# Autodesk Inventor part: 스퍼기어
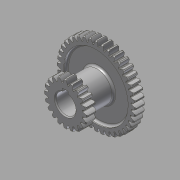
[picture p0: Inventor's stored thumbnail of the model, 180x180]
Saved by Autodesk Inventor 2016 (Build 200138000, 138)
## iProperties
Created: 2015-09
Part Number: 스퍼기어
Material: 강철, 연강
Document SubType Name: Modeling
Designer: mduedu
Density: 7.86 g/cm^3
Mass: 345.726 g
Surface Area: 225.641 cm^2
Volume: 43.9855 cm^3
Appearance: 강철
Author: mduedu
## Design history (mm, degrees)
sketch "스케치1"
  geometry: C1 r 38 at (0, 0); C2 r 40 at (0, 0); C3 r 35.5 at (0, 0); 1 further point
  constraints: 3 centre point, 3 coincident
  dimensions: "d0" = 76 diameter of C1; "d2" = 2 radial gap between concentric circles of C2 C1; "d3" = 71 diameter of C3 (computed from d0)
extrude "돌출1" new body sketch "스케치1" stored distance "d4" = 10; taper "d5" = 0 deg
sketch "스케치2"
  geometry: L1 (0, 35.5)-(0, -35.5); L2 (0, 0)-(40, 0); L3 (0, 0.57)-(39.996, 0.57); L4 (0, 1.57)-(39.969, 1.57); L5 (0, 2.07)-(39.946, 2.07); A1 r 35.5 centre (0, 0) between (0, 35.5) and (0, -35.5) reference; A2 r 40 centre (0, 0) between (40, 0) and (39.946, 2.07) reference; A3 r 9.234 centre (34.93, -7.149) between (39.996, 0.57) and (35.44, 2.07); A4 r 9.234 centre (34.93, 7.149) between (35.44, -2.07) and (39.996, -0.57); A5 r 40 centre (0, 0) between (39.996, -0.57) and (39.996, 0.57); A6 r 35.5 centre (0, 0) between (35.44, -2.07) and (35.44, 2.07); 4 further points
  constraints: 16 point on circle, 10 end point, 6 point on line, 4 centre point, 3 coincident, 3 parallel, 3 symmetric about line, 2 midpoint, 1 perpendicular, 1 vertical, 3 other
  dimensions: "d6" = 0.5 distance between parallel lines of L4 L5; "d8" = 1 distance between parallel lines of L3 L4; "d9" = 1.57 distance between parallel lines of L2 L4
extrude "돌출2" join sketch "스케치2" distance "d10" = 5; taper "d12" = 0 deg; dims "d11" = 5, "d13" = 0
fillet "모깎기1" dims "d17" = 0.5
chamfer "모따기1" distance "d21" = 1; stored, may be unused: second distance "d22" = 2, angle "d23" = 45 deg
sketch "스케치3"
  geometry: C1 r 32.5 at (0, 0); C2 r 15 at (0, 0); 1 further point
  constraints: 2 centre point, 2 coincident
  dimensions: "d27" = 65 diameter of C1; "d28" = 30 diameter of C2
extrude "돌출3" cut sketch "스케치3" distance "d29" = 3; taper "d30" = 0 deg
fillet "모깎기2" dims "d31" = 2
node "작업 평면2"
  node "작업 평면1"
sketch "스케치4"
  geometry: C1 r 15 at (0, 0) reference; 1 further point
extrude "돌출4" join sketch "스케치4" stored distance "d34" = 3; taper "d35" = 0 deg
sketch "스케치5"
  geometry: C1 r 17.5 at (0, 0); C2 r 20 at (0, 0); C3 r 22 at (0, 0); 1 further point
  constraints: 3 centre point, 3 coincident
  dimensions: "d36" = 40 diameter of C2; "d38" = 2 radial gap between concentric circles of C2 C3; "d39" = 35 diameter of C1 (= d36 - 2.5 x d38)
extrude "돌출6" join sketch "스케치5" distance "d46" = 10; taper "d47" = 0 deg
sketch "스케치6"
  geometry: L1 (0, 0)-(0, 22); L2 (-17.5, 0)-(17.5, 0); L3 (-0.57, 0)-(-0.57, 21.993); L4 (-1.57, 0)-(-1.57, 21.944); L5 (-2.07, 0)-(-2.07, 21.902); A1 r 22 centre (0, 0) between (0, 22) and (-0.57, 21.993) reference; A2 r 17.5 centre (0, 0) between (-17.5, 0) and (17.5, 0) reference; A3 r 9.431 centre (7.348, 16.868) between (-0.57, 21.993) and (-2.07, 17.377); A4 r 9.431 centre (-7.348, 16.868) between (2.07, 17.377) and (0.57, 21.993); A5 r 17.5 centre (0, 0) between (2.07, 17.377) and (-2.07, 17.377); A6 r 22 centre (0, 0) between (0.57, 21.993) and (-0.57, 21.993); 4 further points
  constraints: 16 point on circle, 10 end point, 5 point on line, 4 centre point, 3 coincident, 3 symmetric about line, 2 parallel, 2 perpendicular, 1 midpoint, 1 vertical, 3 other
  dimensions: "d40" = 0.5 distance between parallel lines of L4 L5; "d42" = 1 distance between parallel lines of L3 L4; "d43" = 1.57 distance between parallel lines of L1 L4
extrude "돌출5" join sketch "스케치6" distance "d44" = 10; taper "d45" = 0 deg
fillet "모깎기3" dims "d48" = 0.5
chamfer "모따기2" distance "d49" = 1; stored, may be unused: second distance "d50" = 2, angle "d51" = 45 deg
sketch "스케치7"
  geometry: C1 r 10 at (0, 0); 1 further point
  constraints: 1 centre point, 1 coincident
  dimensions: "d55" = 20 diameter of C1
extrude "돌출7" cut sketch "스케치7" stored distance "d56" = 10; taper "d57" = 0 deg
sketch "스케치8"
  geometry: L1 (-9.539, -3)-(-12.8, -3); L2 (-12.8, -3)-(-12.8, 3); L3 (-12.8, 3)-(-9.539, 3); L4 (-9.539, 3)-(-9.539, -3); A1 r 10 centre (0, 0) between (-9.539, -3) and (-9.539, 3) reference; 2 further points
  constraints: 8 end point, 3 point on circle, 2 parallel, 1 horizontal, 1 horizontal alignment, 1 perpendicular
  dimensions: "d58" = 6 distance of L1.end L2.end; "d60" = 22.8 distance from line of point (10, 0) L2
extrude "돌출8" cut sketch "스케치8" stored distance "d61" = 10; taper "d62" = 0 deg
chamfer "모따기3" distance "d63" = 1; stored, may be unused: second distance "d64" = 2, angle "d65" = 45 deg
fillet "모깎기4" dims "d66" = 2
node "솔리드1"
pattern_circular "원형 패턴3" dims "d25" = 360 deg
mirror "대칭1"
pattern_circular "원형 패턴4" dims "d53" = 360 deg
other parameters: "d32" = 9
